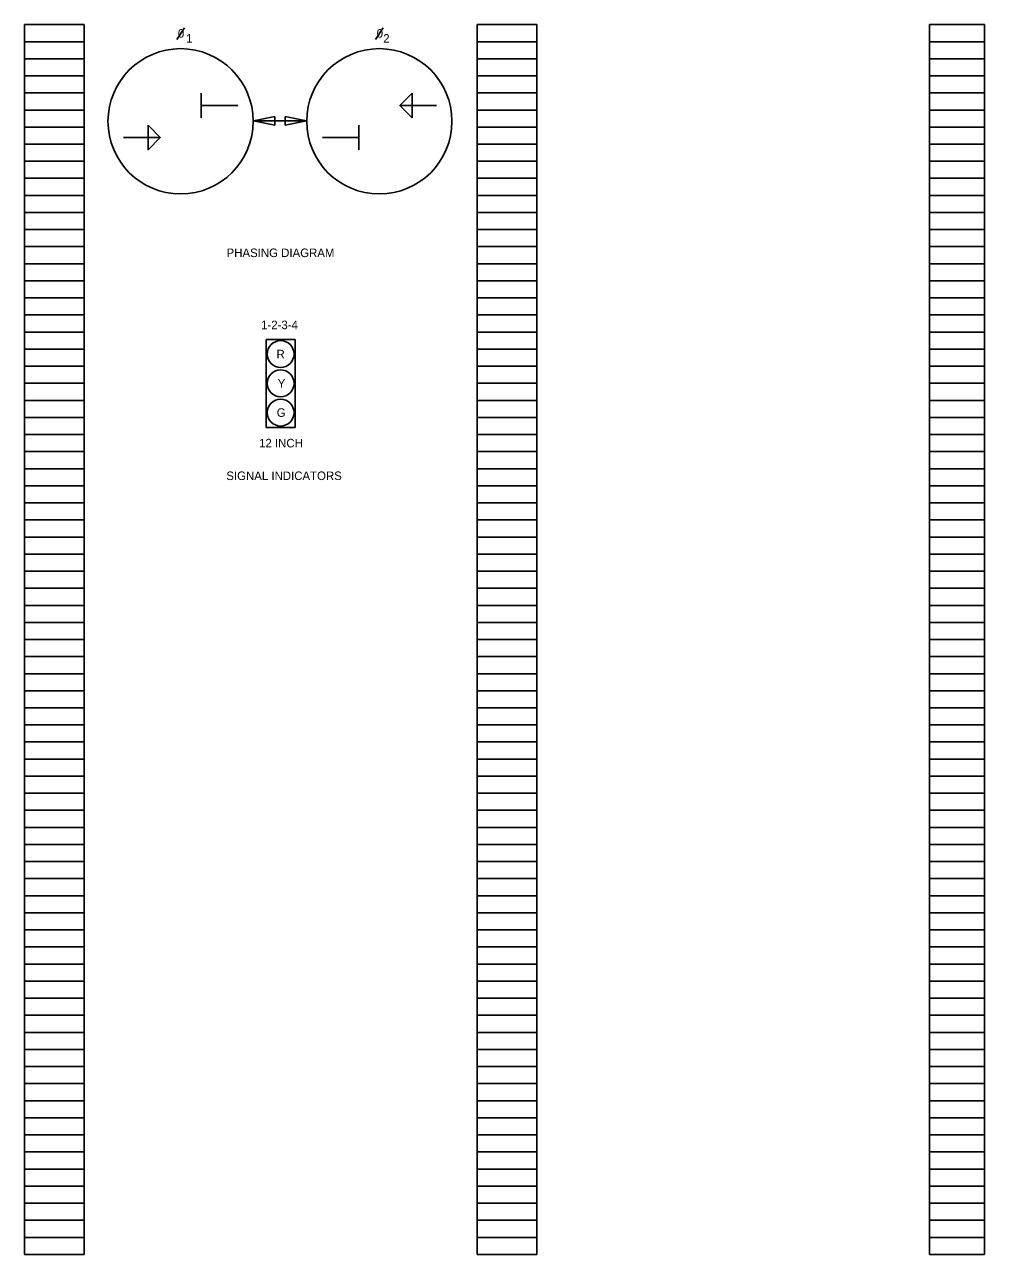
# Model space of a CAD drawing. Extents: x 0 to 74, y -29.1 to 22.
# Drawn here: x 58.26 to 74, y -28.16 to -8 of the extents above; entities that cross this region are included whole.
import ezdxf

# ---------------------------------------------------------------- set-up
doc = ezdxf.new("R2010")
doc.units = 0
for name, color, linetype in [('Default', 7, 'Continuous'), ('SG_P_Heads', 7, 'Continuous'), ('SH_Data', 7, 'Continuous'), ('TX_P_1', 7, 'Continuous')]:
    doc.layers.add(name, color=color, linetype=linetype)

msp = doc.modelspace()

# ---------------------------------------------------------------- linework, layer by layer
at = {"layer": 'Default'}
for p, q in [((62.7, -13.164), (62.221, -13.164)), ((62.221, -13.164), (62.221, -14.606)), ((62.7, -14.606), (62.7, -13.164)), ((62.221, -14.606), (62.7, -14.606))]:
    msp.add_line(p, q, dxfattribs=at)
for centre in [(62.459, -13.401), (62.459, -13.881), (62.459, -14.36)]:
    msp.add_circle(centre, 0.22, dxfattribs=at)
at = {"layer": 'SG_P_Heads'}
for p, q in [((61.155, -9.126), (61.155, -9.526)), ((61.755, -9.326), (61.155, -9.326)), ((65.014, -9.326), (64.414, -9.326)), ((63.744, -10.051), (63.744, -9.651)), ((59.884, -9.851), (60.485, -9.851)), ((63.143, -9.851), (63.744, -9.851))]:
    msp.add_line(p, q, dxfattribs=at)
for points in [[(64.614, -9.526), (64.414, -9.326), (64.614, -9.126)], [(60.285, -9.651), (60.485, -9.851), (60.285, -10.051)], [(62.362, -9.647), (62.012, -9.577), (62.362, -9.507)], [(62.536, -9.507), (62.886, -9.577), (62.536, -9.647)]]:
    msp.add_lwpolyline(points, close=True, dxfattribs=at)
at = {"layer": 'SH_Data'}
for p, q in [((58.26, -28.16), (58.26, -8)), ((58.26, -8), (59.24, -8)), ((59.24, -28.16), (59.24, -8)), ((65.68, -28.16), (65.68, -8)), ((65.68, -8), (66.66, -8)), ((66.66, -28.16), (66.66, -8)), ((73.1, -28.16), (73.1, -8)), ((73.1, -8), (74, -8)), ((74, -28.16), (74, -8)), ((58.26, -8.28), (59.24, -8.28)), ((65.68, -8.28), (66.66, -8.28)), ((73.1, -8.28), (74, -8.28)), ((58.26, -8.56), (59.24, -8.56)), ((65.68, -8.56), (66.66, -8.56)), ((73.1, -8.56), (74, -8.56)), ((58.26, -8.84), (59.24, -8.84)), ((65.68, -8.84), (66.66, -8.84)), ((73.1, -8.84), (74, -8.84)), ((58.26, -9.12), (59.24, -9.12)), ((65.68, -9.12), (66.66, -9.12)), ((73.1, -9.12), (74, -9.12)), ((58.26, -9.4), (59.24, -9.4)), ((65.68, -9.4), (66.66, -9.4)), ((73.1, -9.4), (74, -9.4)), ((62.886, -9.577), (62.012, -9.577)), ((58.26, -9.68), (59.24, -9.68)), ((65.68, -9.68), (66.66, -9.68)), ((73.1, -9.68), (74, -9.68)), ((58.26, -9.96), (59.24, -9.96)), ((65.68, -9.96), (66.66, -9.96)), ((73.1, -9.96), (74, -9.96)), ((58.26, -10.24), (59.24, -10.24)), ((65.68, -10.24), (66.66, -10.24)), ((73.1, -10.24), (74, -10.24)), ((58.26, -10.52), (59.24, -10.52)), ((65.68, -10.52), (66.66, -10.52)), ((73.1, -10.52), (74, -10.52)), ((58.26, -10.8), (59.24, -10.8)), ((65.68, -10.8), (66.66, -10.8)), ((73.1, -10.8), (74, -10.8)), ((58.26, -11.08), (59.24, -11.08)), ((65.68, -11.08), (66.66, -11.08)), ((73.1, -11.08), (74, -11.08)), ((58.26, -11.36), (59.24, -11.36)), ((65.68, -11.36), (66.66, -11.36)), ((73.1, -11.36), (74, -11.36)), ((58.26, -11.64), (59.24, -11.64)), ((65.68, -11.64), (66.66, -11.64)), ((73.1, -11.64), (74, -11.64)), ((58.26, -11.92), (59.24, -11.92)), ((65.68, -11.92), (66.66, -11.92)), ((73.1, -11.92), (74, -11.92)), ((58.26, -12.2), (59.24, -12.2)), ((65.68, -12.2), (66.66, -12.2)), ((73.1, -12.2), (74, -12.2)), ((58.26, -12.48), (59.24, -12.48)), ((65.68, -12.48), (66.66, -12.48)), ((73.1, -12.48), (74, -12.48)), ((58.26, -12.76), (59.24, -12.76)), ((65.68, -12.76), (66.66, -12.76)), ((73.1, -12.76), (74, -12.76)), ((58.26, -13.04), (59.24, -13.04)), ((65.68, -13.04), (66.66, -13.04)), ((73.1, -13.04), (74, -13.04)), ((58.26, -13.32), (59.24, -13.32)), ((65.68, -13.32), (66.66, -13.32)), ((73.1, -13.32), (74, -13.32)), ((58.26, -13.6), (59.24, -13.6)), ((65.68, -13.6), (66.66, -13.6)), ((73.1, -13.6), (74, -13.6)), ((58.26, -13.88), (59.24, -13.88)), ((65.68, -13.88), (66.66, -13.88)), ((73.1, -13.88), (74, -13.88)), ((58.26, -14.16), (59.24, -14.16)), ((65.68, -14.16), (66.66, -14.16)), ((73.1, -14.16), (74, -14.16)), ((58.26, -14.44), (59.24, -14.44)), ((65.68, -14.44), (66.66, -14.44)), ((73.1, -14.44), (74, -14.44)), ((58.26, -14.72), (59.24, -14.72)), ((65.68, -14.72), (66.66, -14.72)), ((73.1, -14.72), (74, -14.72)), ((58.26, -15), (59.24, -15)), ((65.68, -15), (66.66, -15)), ((73.1, -15), (74, -15)), ((58.26, -15.28), (59.24, -15.28)), ((65.68, -15.28), (66.66, -15.28)), ((73.1, -15.28), (74, -15.28)), ((58.26, -15.56), (59.24, -15.56)), ((65.68, -15.56), (66.66, -15.56)), ((73.1, -15.56), (74, -15.56)), ((58.26, -15.84), (59.24, -15.84)), ((65.68, -15.84), (66.66, -15.84)), ((73.1, -15.84), (74, -15.84)), ((58.26, -16.12), (59.24, -16.12)), ((65.68, -16.12), (66.66, -16.12)), ((73.1, -16.12), (74, -16.12)), ((58.26, -16.4), (59.24, -16.4)), ((65.68, -16.4), (66.66, -16.4)), ((73.1, -16.4), (74, -16.4)), ((58.26, -16.68), (59.24, -16.68)), ((65.68, -16.68), (66.66, -16.68)), ((73.1, -16.68), (74, -16.68)), ((58.26, -16.96), (59.24, -16.96)), ((65.68, -16.96), (66.66, -16.96)), ((73.1, -16.96), (74, -16.96)), ((58.26, -17.24), (59.24, -17.24)), ((65.68, -17.24), (66.66, -17.24)), ((73.1, -17.24), (74, -17.24)), ((58.26, -17.52), (59.24, -17.52)), ((65.68, -17.52), (66.66, -17.52)), ((73.1, -17.52), (74, -17.52)), ((58.26, -17.8), (59.24, -17.8)), ((65.68, -17.8), (66.66, -17.8)), ((73.1, -17.8), (74, -17.8)), ((58.26, -18.08), (59.24, -18.08)), ((65.68, -18.08), (66.66, -18.08)), ((73.1, -18.08), (74, -18.08)), ((58.26, -18.36), (59.24, -18.36)), ((65.68, -18.36), (66.66, -18.36)), ((73.1, -18.36), (74, -18.36)), ((58.26, -18.64), (59.24, -18.64)), ((65.68, -18.64), (66.66, -18.64)), ((73.1, -18.64), (74, -18.64)), ((58.26, -18.92), (59.24, -18.92)), ((65.68, -18.92), (66.66, -18.92)), ((73.1, -18.92), (74, -18.92)), ((58.26, -19.2), (59.24, -19.2)), ((65.68, -19.2), (66.66, -19.2)), ((73.1, -19.2), (74, -19.2)), ((58.26, -19.48), (59.24, -19.48)), ((65.68, -19.48), (66.66, -19.48)), ((73.1, -19.48), (74, -19.48)), ((58.26, -19.76), (59.24, -19.76)), ((65.68, -19.76), (66.66, -19.76)), ((73.1, -19.76), (74, -19.76)), ((58.26, -20.04), (59.24, -20.04)), ((65.68, -20.04), (66.66, -20.04)), ((73.1, -20.04), (74, -20.04)), ((58.26, -20.32), (59.24, -20.32)), ((65.68, -20.32), (66.66, -20.32)), ((73.1, -20.32), (74, -20.32)), ((58.26, -20.6), (59.24, -20.6)), ((65.68, -20.6), (66.66, -20.6)), ((73.1, -20.6), (74, -20.6)), ((58.26, -20.88), (59.24, -20.88)), ((65.68, -20.88), (66.66, -20.88)), ((73.1, -20.88), (74, -20.88)), ((58.26, -21.16), (59.24, -21.16)), ((65.68, -21.16), (66.66, -21.16)), ((73.1, -21.16), (74, -21.16)), ((58.26, -21.44), (59.24, -21.44)), ((65.68, -21.44), (66.66, -21.44)), ((73.1, -21.44), (74, -21.44)), ((58.26, -21.72), (59.24, -21.72)), ((65.68, -21.72), (66.66, -21.72)), ((73.1, -21.72), (74, -21.72)), ((58.26, -22), (59.24, -22)), ((65.68, -22), (66.66, -22)), ((73.1, -22), (74, -22)), ((58.26, -22.28), (59.24, -22.28)), ((65.68, -22.28), (66.66, -22.28)), ((73.1, -22.28), (74, -22.28)), ((58.26, -22.56), (59.24, -22.56)), ((65.68, -22.56), (66.66, -22.56)), ((73.1, -22.56), (74, -22.56)), ((58.26, -22.84), (59.24, -22.84)), ((65.68, -22.84), (66.66, -22.84)), ((73.1, -22.84), (74, -22.84)), ((58.26, -23.12), (59.24, -23.12)), ((65.68, -23.12), (66.66, -23.12)), ((73.1, -23.12), (74, -23.12)), ((58.26, -23.4), (59.24, -23.4)), ((65.68, -23.4), (66.66, -23.4)), ((73.1, -23.4), (74, -23.4)), ((58.26, -23.68), (59.24, -23.68)), ((65.68, -23.68), (66.66, -23.68)), ((73.1, -23.68), (74, -23.68)), ((58.26, -23.96), (59.24, -23.96)), ((65.68, -23.96), (66.66, -23.96)), ((73.1, -23.96), (74, -23.96)), ((58.26, -24.24), (59.24, -24.24)), ((65.68, -24.24), (66.66, -24.24)), ((73.1, -24.24), (74, -24.24)), ((58.26, -24.52), (59.24, -24.52)), ((65.68, -24.52), (66.66, -24.52)), ((73.1, -24.52), (74, -24.52)), ((58.26, -24.8), (59.24, -24.8)), ((65.68, -24.8), (66.66, -24.8)), ((73.1, -24.8), (74, -24.8)), ((58.26, -25.08), (59.24, -25.08)), ((65.68, -25.08), (66.66, -25.08)), ((73.1, -25.08), (74, -25.08)), ((58.26, -25.36), (59.24, -25.36)), ((65.68, -25.36), (66.66, -25.36)), ((73.1, -25.36), (74, -25.36)), ((58.26, -25.64), (59.24, -25.64)), ((65.68, -25.64), (66.66, -25.64)), ((73.1, -25.64), (74, -25.64)), ((58.26, -25.92), (59.24, -25.92)), ((65.68, -25.92), (66.66, -25.92)), ((73.1, -25.92), (74, -25.92)), ((58.26, -26.2), (59.24, -26.2)), ((65.68, -26.2), (66.66, -26.2)), ((73.1, -26.2), (74, -26.2)), ((58.26, -26.48), (59.24, -26.48)), ((65.68, -26.48), (66.66, -26.48)), ((73.1, -26.48), (74, -26.48)), ((58.26, -26.76), (59.24, -26.76)), ((65.68, -26.76), (66.66, -26.76)), ((73.1, -26.76), (74, -26.76)), ((58.26, -27.04), (59.24, -27.04)), ((65.68, -27.04), (66.66, -27.04)), ((73.1, -27.04), (74, -27.04)), ((58.26, -27.32), (59.24, -27.32)), ((65.68, -27.32), (66.66, -27.32)), ((73.1, -27.32), (74, -27.32)), ((58.26, -27.6), (59.24, -27.6)), ((65.68, -27.6), (66.66, -27.6)), ((73.1, -27.6), (74, -27.6)), ((58.26, -27.88), (59.24, -27.88)), ((65.68, -27.88), (66.66, -27.88)), ((73.1, -27.88), (74, -27.88)), ((58.26, -28.16), (59.24, -28.16)), ((65.68, -28.16), (66.66, -28.16)), ((73.1, -28.16), (74, -28.16))]:
    msp.add_line(p, q, dxfattribs=at)
for centre in [(60.819, -9.585), (64.078, -9.585)]:
    msp.add_circle(centre, 1.191, dxfattribs=at)
at = {"layer": 'TX_P_1'}
for p, q in [((60.884, -8.052), (60.758, -8.244)), ((64.143, -8.052), (64.017, -8.244))]:
    msp.add_line(p, q, dxfattribs=at)

# ---------------------------------------------------------------- texts
at = {"layer": 'Default'}
for s, p in [('R', (62.392, -13.471)), ('Y', (62.411, -13.951)), ('G', (62.395, -14.43)), ('SIGNAL INDICATORS', (61.569, -15.466))]:
    msp.add_text(s, height=0.14, dxfattribs=at).set_placement(p)
at = {"layer": 'SH_Data'}
msp.add_text('0', height=0.14, dxfattribs=at).set_placement((60.775, -8.214))
at = {"layer": 'TX_P_1'}
for s, p in [('1', (60.908, -8.296)), ('0', (64.034, -8.214)), ('2', (64.142, -8.296)), ('PHASING DIAGRAM', (61.573, -11.811)), ('1-2-3-4', (62.139, -12.993)), ('12 INCH', (62.106, -14.931))]:
    msp.add_text(s, height=0.14, dxfattribs=at).set_placement(p)

doc.saveas('drawing.dxf')
